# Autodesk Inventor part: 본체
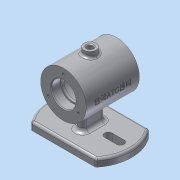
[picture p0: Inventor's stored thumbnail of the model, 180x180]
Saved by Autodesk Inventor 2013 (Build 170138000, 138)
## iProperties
Created: 2017-12
Part Number: 본체
Material: 알루미늄 6061
Document SubType Name: Modeling
Designer: dgall
Mass: 461.045 g
Surface Area: 485.091 cm^2
Volume: 170.127 cm^3
Density: 2.71 g/cm^3
Author: dgall
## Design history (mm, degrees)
sketch "스케치1"
  geometry: L1 (0, 0)-(70, 0); L2 (0, 0)-(0, 30); L3 (0, 30)-(70, 30); L4 (70, 30)-(70, 0); L5 (0, 16)-(11.7, 16); L6 (12, 15.7)-(12, 14); L7 (12, 14)-(15, 14); L8 (15, 14)-(15, 22); L9 (18, 25)-(52, 25); L10 (55, 22)-(55, 14); L11 (55, 14)-(58, 14); L12 (58, 14)-(58, 15.7); L13 (58.3, 16)-(70, 16); A1 r 3 centre (18, 22) between (18, 25) and (15, 22); A2 r 3 centre (52, 22) between (55, 22) and (52, 25); A3 r 0.3 centre (11.7, 15.7) between (12, 15.7) and (11.7, 16); A4 r 0.3 centre (58.3, 15.7) between (58.3, 16) and (58, 15.7); 5 further points
  constraints: 27 end point, 10 point on line, 8 point on circle, 8 tangent, 6 parallel, 5 perpendicular, 4 centre point, 2 collinear, 1 coincident, 1 equal radius, 1 horizontal
  dimensions: "d0" = 70 distance of L1.start L1.end; "d2" = 50 diameter of L9 L1; "d3" = 12 distance of L5.start point (12, 16); "d4" = 40 distance of point (15, 25) point (55, 25); "d5" = 12 distance of point (58, 16) L13.end; "d6" = 32 diameter of L5 L1; "d7" = 32 diameter of L13 L1; "d8" = 28 diameter of L11 L1; "d9" = 28 diameter of L7 L1; "d10" = 60 diameter of L3 L1; "d11" = 3 radius of A1; "d12" = 0.3 radius of A3; "d13" = 0.3 radius of A4
revolve "회전1" sketch "스케치1" stored, may be unused: angle "d14" = 90 deg
chamfer "모따기1" distance "d15" = 1; stored, may be unused: second distance "d16" = 2, angle "d17" = 45 deg
node "작업 평면1"
sketch "스케치2"
  geometry: L1 (0, -30)-(0, 30) reference; L2 (0, 42.426)-(0, -42.426); L3 (70, 42.426)-(70, -42.426); L4 (0, 30)-(70, 30) reference; A1 r 55 centre (35, 0) between (0, 42.426) and (0, -42.426); 3 further points
  constraints: 4 end point, 4 point on circle, 2 midpoint, 2 parallel, 1 centre point, 1 collinear, 1 horizontal alignment, 1 vertical alignment
  dimensions: "d19" = 110 diameter of A1; "d20" = 70 distance between parallel lines of L3 L2
extrude "돌출1" join sketch "스케치2" distance "d21" = 10; taper "d22" = 0 deg
sketch "스케치3"
  geometry: L1 (0, 17)-(-1, 16) reference; L2 (-1, 16)-(-11.7, 16) reference; L3 (-12, 15.7)-(-12, 14) reference; L4 (-12, 14)-(-15, 14) reference; L5 (-15, 14)-(-15, 22) reference; L6 (-18, 25)-(-52, 25) reference; L7 (-55, 22)-(-55, 14) reference; L8 (-55, 14)-(-58, 14) reference; L9 (-58, 14)-(-58, 15.7) reference; L10 (-58.3, 16)-(-69, 16) reference; L11 (-69, 16)-(-70, 17) reference; L12 (-70, 17)-(-70, 30) reference; L13 (-70, 30)-(0, 30) reference; L14 (0, 30)-(0, 17) reference; L15 (-1, -16)-(0, -17) reference; L16 (0, -17)-(0, -30) reference; L17 (0, -30)-(-70, -30) reference; L18 (-70, -30)-(-70, -17) reference; L19 (-70, -17)-(-69, -16) reference; L20 (-69, -16)-(-58.3, -16) reference; L21 (-58, -15.7)-(-58, -14) reference; L22 (-58, -14)-(-55, -14) reference; L23 (-55, -14)-(-55, -22) reference; L24 (-52, -25)-(-18, -25) reference; L25 (-15, -22)-(-15, -14) reference; L26 (-15, -14)-(-12, -14) reference; L27 (-12, -14)-(-12, -15.7) reference; L28 (-11.7, -16)-(-1, -16) reference; L29 (0, -52)-(0, -62) reference; L30 (0, -62)-(-70, -62) reference; L31 (-70, -62)-(-70, -52) reference; L32 (-70, -52)-(0, -52) reference; L33 (-50, -27)-(-50, -52); L34 (0, -52)-(-70, -52) reference; L35 (-50, -27)-(-20, -27); L36 (-20, -27)-(-20, -52); L37 (-20, -52)-(-50, -52); A1 r 0.3 centre (-11.7, 15.7) between (-11.7, 16) and (-12, 15.7) reference; A2 r 3 centre (-18, 22) between (-15, 22) and (-18, 25) reference; A3 r 3 centre (-52, 22) between (-52, 25) and (-55, 22) reference; A4 r 0.3 centre (-58.3, 15.7) between (-58, 15.7) and (-58.3, 16) reference; A5 r 0.3 centre (-58.3, -15.7) between (-58.3, -16) and (-58, -15.7) reference; A6 r 3 centre (-52, -22) between (-55, -22) and (-52, -25) reference; A7 r 3 centre (-18, -22) between (-18, -25) and (-15, -22) reference; A8 r 0.3 centre (-11.7, -15.7) between (-12, -15.7) and (-11.7, -16) reference; 3 further points
  constraints: 8 end point, 3 perpendicular, 2 midpoint, 2 point on line, 1 collinear, 1 vertical alignment
  dimensions: "d23" = 30 distance of L33.start L35.end; "d25" = 25 distance of L35.end L36.end
extrude "돌출2" join sketch "스케치3" stored distance "d26" = 10; taper "d27" = 0 deg
sketch "스케치4"
  geometry: C1 r 30 at (0, 0) reference; 1 further point
  constraints: 1 horizontal alignment
  dimensions: "d28" = 23 distance of point (-23, 0) C1.centre
hole "구멍1" sketch "스케치4" at (-23, 0) diameter "d29" = 3.242; stored, may be unused: countersink angle "d33" = 90 deg, drill point angle "d35" = 118 deg; dims "d30" = 8, "d31" = 4, "d32" = 2, "d34" = 10
node "작업 평면2"
node "작업 평면3"
sketch "스케치5"
  geometry: L1 (0, -30)-(0, 30) reference; C1 r 8 at (35, 0); 1 further point
  constraints: 1 centre point, 1 horizontal alignment
  dimensions: "d40" = 16 diameter of C1; "d41" = 35 distance from line of C1.centre L1
extrude "돌출3" join sketch "스케치5" stored distance "d42" = 10; taper "d43" = 0 deg
hole "구멍2" diameter "d46" = 8; stored, may be unused: countersink angle "d50" = 90 deg, drill point angle "d52" = 0 deg; dims "d44" = 10, "d45" = 10, "d47" = 8, "d48" = 4, "d49" = 2, "d51" = 10
chamfer "모따기2" distance "d53" = 1; stored, may be unused: second distance "d54" = 2, angle "d55" = 45 deg
fillet "모깎기1" dims "d56" = 5
fillet "모깎기2" dims "d57" = 5
fillet "모깎기3" dims "d58" = 3
fillet "모깎기4" dims "d59" = 3
sketch "스케치6"
  geometry: L1 (67, 40.988)-(67, -40.988) reference; L2 (30, 40)-(30, 24); L3 (40, 24)-(40, 40); A1 r 10 centre (45, 0) between (45, -10) and (45, 10) reference; A2 r 52 centre (35, 0) between (3, -40.988) and (67, -40.988) reference; A3 r 5 centre (35, 24) between (30, 24) and (40, 24); A4 r 5 centre (35, 40) between (40, 40) and (30, 40); 1 further point
  constraints: 4 end point, 4 point on circle, 4 tangent, 2 centre point, 2 parallel, 2 vertical alignment
  dimensions: "d60" = 5 radius of A4; "d62" = 16 distance of A3.centre A4.centre; "d63" = 24 vertical distance of A1.centre A3.centre
extrude "돌출4" cut sketch "스케치6" stored distance "d64" = 10; taper "d65" = 0 deg
node "작업 평면4"
sketch "스케치7"
  geometry: L1 (-70, 30)-(-70, -30) reference; 2 further points
  constraints: 1 other
  dimensions: "d67" = 35 distance from line of L1 point (-35, 0); "d68" = 30 vertical distance of L1.start point (-35, 0)
feature "엠보싱1" sketch "스케치7" dims "d0" = 70, "d2" = 50, "d3" = 12, "d4" = 40, "d5" = 12, "d6" = 32, "d7" = 32, "d8" = 28, "d9" = 28, "d10" = 60, "d11" = 3, "d12" = 0.3, "d13" = 0.3, "d69" = 0.5, "d70" = 0
fillet "모깎기5" dims "d71" = 3
node "솔리드1"
pattern_circular "원형 패턴1" dims angle "d37" = 360 deg
mirror "대칭1"
mirror "대칭2"
node "절단 모서리 투영1"
other parameters: "d18" = -62, "d39" = 37
